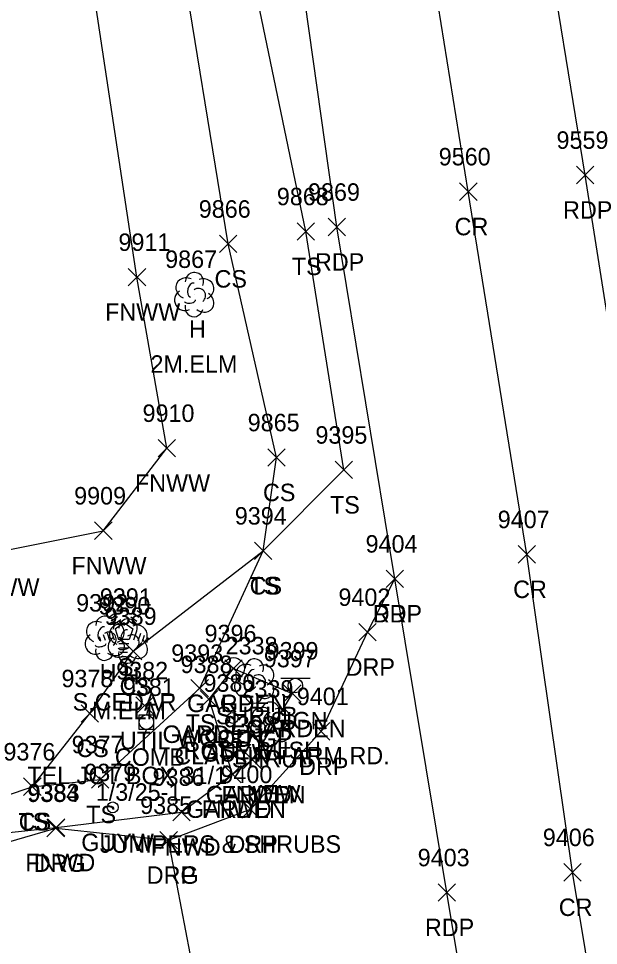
# Model space of a CAD drawing. Extents: x 1439173 to 1457902, y 641926 to 659889.
# Drawn here: x 1448183.7 to 1448250.2, y 646625.5 to 646731.6 of the extents above; entities that cross this region are included whole.
import ezdxf

# ---------------------------------------------------------------- set-up
doc = ezdxf.new("R2010")
doc.units = 0
for name, color, linetype in [('L_A', 7, 'Continuous'), ('L_C', 7, 'Continuous'), ('L_I', 7, 'Continuous'), ('L_TIC', 7, 'Continuous'), ('LAPB', 7, 'Continuous'), ('LELB', 7, 'Continuous'), ('LFNC', 7, 'Continuous'), ('LSH', 7, 'Continuous'), ('LTC', 7, 'Continuous'), ('LTD', 7, 'Continuous'), ('P_A', 7, 'Continuous'), ('P_I', 7, 'Continuous'), ('P_TIC', 7, 'Continuous'), ('PET', 7, 'Continuous'), ('PRC', 7, 'Continuous'), ('R_A', 7, 'Continuous'), ('R_I', 7, 'Continuous'), ('R_TIC', 7, 'Continuous'), ('RDG', 7, 'Continuous'), ('RDP', 7, 'Continuous'), ('RGP', 7, 'Continuous'), ('S_A', 7, 'Continuous'), ('S_C', 7, 'Continuous'), ('S_I', 7, 'Continuous'), ('SSGN', 7, 'Continuous'), ('U_A', 7, 'Continuous'), ('U_C', 7, 'Continuous'), ('U_I', 7, 'Continuous'), ('UDEFAULT', 7, 'Continuous'), ('UP', 7, 'Continuous'), ('UPGW', 7, 'Continuous')]:
    doc.layers.add(name, color=color, linetype=linetype)

msp = doc.modelspace()

# ---------------------------------------------------------------- linework, layer by layer
at = {"layer": 'L_TIC'}
for points in [[(1448215.65, 646706.27), (1448217.65, 646708.27)], [(1448217.65, 646706.27), (1448215.65, 646708.27)], [(1448206.76, 646704.84), (1448208.76, 646706.84)], [(1448208.76, 646704.84), (1448206.76, 646706.84)], [(1448196.31, 646701.04), (1448198.31, 646703.04)], [(1448198.31, 646701.04), (1448196.31, 646703.04)], [(1448199.73, 646681.46), (1448201.73, 646683.46)], [(1448201.73, 646681.46), (1448199.73, 646683.46)], [(1448212.3, 646680.39), (1448214.3, 646682.39)], [(1448214.3, 646680.39), (1448212.3, 646682.39)], [(1448220.02, 646678.97), (1448222.02, 646680.97)], [(1448222.02, 646678.97), (1448220.02, 646680.97)], [(1448220.02, 646678.97), (1448222.02, 646680.97)], [(1448222.02, 646678.97), (1448220.02, 646680.97)], [(1448192.45, 646672.01), (1448194.45, 646674.01)], [(1448194.45, 646672.01), (1448192.45, 646674.01)], [(1448210.78, 646669.71), (1448212.78, 646671.71)], [(1448212.78, 646669.71), (1448210.78, 646671.71)], [(1448210.78, 646669.71), (1448212.78, 646671.71)], [(1448212.78, 646669.71), (1448210.78, 646671.71)], [(1448195.88, 646658.22), (1448197.88, 646660.22)], [(1448197.88, 646658.22), (1448195.88, 646660.22)], [(1448207.38, 646656.24), (1448209.38, 646658.24)], [(1448209.38, 646656.24), (1448207.38, 646658.24)], [(1448203.5, 646653.99), (1448205.5, 646655.99)], [(1448205.5, 646653.99), (1448203.5, 646655.99)], [(1448214.11, 646653.37), (1448216.11, 646655.37)], [(1448216.11, 646653.37), (1448214.11, 646655.37)], [(1448204.57, 646652.71), (1448206.57, 646654.71)], [(1448206.57, 646652.71), (1448204.57, 646654.71)], [(1448190.92, 646651.09), (1448192.92, 646653.09)], [(1448192.92, 646651.09), (1448190.92, 646653.09)], [(1448209.53, 646645.79), (1448211.53, 646647.79)], [(1448211.53, 646645.79), (1448209.53, 646647.79)], [(1448209.53, 646645.79), (1448211.53, 646647.79)], [(1448211.53, 646645.79), (1448209.53, 646647.79)], [(1448192.09, 646643.53), (1448194.09, 646645.53)], [(1448194.09, 646643.53), (1448192.09, 646645.53)], [(1448207.27, 646644.13), (1448209.27, 646646.13)], [(1448209.27, 646644.13), (1448207.27, 646646.13)], [(1448207.27, 646644.13), (1448209.27, 646646.13)], [(1448209.27, 646644.13), (1448207.27, 646646.13)], [(1448184.32, 646642.7), (1448186.32, 646644.7)], [(1448186.32, 646642.7), (1448184.32, 646644.7)], [(1448184.32, 646642.7), (1448186.32, 646644.7)], [(1448186.32, 646642.7), (1448184.32, 646644.7)], [(1448201.42, 646639.8), (1448203.42, 646641.8)], [(1448203.42, 646639.8), (1448201.42, 646641.8)], [(1448187.05, 646638.02), (1448189.05, 646640.02)], [(1448189.05, 646638.02), (1448187.05, 646640.02)]]:
    msp.add_lwpolyline(points, dxfattribs=at)
at = {"layer": 'LAPB'}
msp.add_lwpolyline([(1448208.27, 646645.13), (1448205.57, 646653.71), (1448208.38, 646657.24), (1448215.11, 646654.37), (1448210.53, 646646.79)], dxfattribs=at)
at = {"layer": 'LELB'}
for points in [[(1448221.02, 646679.97), (1448216.65, 646707.27), (1448209.17, 646743.3), (1448202.24, 646783.83), (1448197.14, 646815.73), (1448192.88, 646849.23), (1448188.79, 646883.91), (1448185.57, 646916.7), (1448180.61, 646928.95), (1448176.05, 646935.8), (1448168.91, 646942.17), (1448163.03, 646939.76)], [(1448185.32, 646643.7), (1448191.92, 646652.09), (1448196.88, 646659.22), (1448211.78, 646670.71), (1448213.3, 646681.39), (1448207.76, 646705.84), (1448201.91, 646741.7), (1448196.92, 646782.31), (1448195.88, 646813.4), (1448188.29, 646849.33)], [(1448098.23, 646630.31), (1448120.23, 646632.42), (1448150.79, 646634.85), (1448163.88, 646636.49), (1448185.32, 646643.7), (1448193.09, 646644.53), (1448204.5, 646654.99), (1448211.78, 646670.71), (1448221.02, 646679.97)]]:
    msp.add_lwpolyline(points, dxfattribs=at)
at = {"layer": 'LFNC'}
for points in [[(1448099.82, 646655.95), (1448102.02, 646656.12), (1448112.07, 646658.89), (1448125.11, 646661.46), (1448146.72, 646665.17), (1448181.19, 646670.55), (1448193.45, 646673.01), (1448200.73, 646682.46), (1448197.31, 646702.04), (1448191.65, 646739.49), (1448183.01, 646786), (1448178.86, 646809.45), (1448173.13, 646841), (1448169.61, 646862.71), (1448166.95, 646881.82), (1448157.08, 646891.59), (1448153.58, 646895.82), (1448145.42, 646911.6)], [(1448163.88, 646636.49), (1448188.05, 646639.02), (1448202.42, 646640.8), (1448208.27, 646645.13), (1448210.53, 646646.79)]]:
    msp.add_lwpolyline(points, dxfattribs=at)
at = {"layer": 'LSH'}
for p, q in [((1448210.73, 646655.85), (1448210.73, 646655.85)), ((1448210.73, 646655.85), (1448210.73, 646655.85)), ((1448212.56, 646650.9), (1448212.56, 646650.9)), ((1448212.56, 646650.9), (1448212.56, 646650.9))]:
    msp.add_line(p, q, dxfattribs=at)
for centre in [(1448210.77, 646657.28), (1448212.6, 646652.34)]:
    msp.add_arc(centre, 1.05, 335.5272, 180.9563, dxfattribs=at)
for centre, major_axis, ratio, start_param, end_param in [((1448209.93, 646656.51), (1.21, -0.51), 0.895232, 1.570796, 4.712389), ((1448210.52, 646656.31), (-0.208, -0.792), 0.645439, 3.141593, 6.283185), ((1448211.77, 646656.43), (-1.14, -0.48), 0.949671, 1.570796, 4.712389), ((1448209.64, 646655.14), (0.58, -1.04), 0.959034, 3.141593, 6.283185), ((1448211.23, 646655.68), (-0.5, 0.667), 0.989748, 3.141593, 6.283185), ((1448210.27, 646655.1), (-0.625, -0.083), 0.423636, 0, 3.141593), ((1448211.73, 646655.01), (-1.09, 0.79), 0.841452, 1.570796, 4.712389), ((1448210.73, 646654.35), (0.26, 1.06), 0.942809, 1.570796, 4.712389), ((1448211.77, 646651.57), (1.21, -0.51), 0.895232, 1.570796, 4.712389), ((1448213.6, 646651.49), (-1.14, -0.48), 0.949671, 1.570796, 4.712389), ((1448212.35, 646651.36), (-0.208, -0.792), 0.645439, 3.141593, 6.283185), ((1448211.47, 646650.19), (0.58, -1.04), 0.959034, 3.141593, 6.283185), ((1448213.06, 646650.74), (-0.5, 0.667), 0.989748, 3.141593, 6.283185), ((1448213.56, 646650.07), (-1.09, 0.79), 0.841452, 1.570796, 4.712389), ((1448212.56, 646649.4), (0.26, 1.06), 0.942809, 1.570796, 4.712389), ((1448212.1, 646650.15), (-0.625, -0.083), 0.423636, 0, 3.141593)]:
    msp.add_ellipse(centre, major_axis=major_axis, ratio=ratio, start_param=start_param, end_param=end_param, dxfattribs=at)
at = {"layer": 'LTC'}
for p, q in [((1448193.95, 646663.62), (1448194.31, 646663.87)), ((1448194.16, 646663.15), (1448194.69, 646663.53)), ((1448196.98, 646663.51), (1448197.53, 646663.11)), ((1448197.35, 646663.86), (1448197.77, 646663.55)), ((1448194.37, 646662.68), (1448195.08, 646663.2)), ((1448194.58, 646662.22), (1448195.46, 646662.86)), ((1448194.81, 646661.76), (1448195.82, 646662.5)), ((1448195.82, 646662.5), (1448196.82, 646661.77)), ((1448196.24, 646662.81), (1448197.05, 646662.22)), ((1448196.61, 646663.16), (1448197.29, 646662.67)), ((1448193.9, 646661.33), (1448194.17, 646660.49)), ((1448194.35, 646661.54), (1448194.68, 646660.53)), ((1448194.81, 646661.76), (1448195.19, 646660.57)), ((1448196.82, 646661.77), (1448196.42, 646660.57)), ((1448197.25, 646661.5), (1448196.91, 646660.46)), ((1448197.7, 646661.25), (1448197.41, 646660.37)), ((1448192.99, 646660.89), (1448193.14, 646660.43)), ((1448193.44, 646661.11), (1448193.65, 646660.46)), ((1448196.42, 646660.57), (1448195.19, 646660.57)), ((1448198.14, 646661), (1448197.9, 646660.27)), ((1448198.59, 646660.75), (1448198.4, 646660.18)), ((1448196.39, 646660.07), (1448195.24, 646660.07)), ((1448196.3, 646659.57), (1448195.31, 646659.57)), ((1448196.22, 646659.07), (1448195.39, 646659.07)), ((1448196.13, 646658.57), (1448195.46, 646658.57))]:
    msp.add_line(p, q, dxfattribs=at)
at = {"layer": 'LTD'}
for p, q in [((1448203.85, 646700.09), (1448203.85, 646700.09)), ((1448203.85, 646700.09), (1448203.85, 646700.09)), ((1448193.6, 646660.75), (1448193.6, 646660.75)), ((1448193.6, 646660.75), (1448193.6, 646660.75)), ((1448196.24, 646660.42), (1448196.24, 646660.42)), ((1448196.24, 646660.42), (1448196.24, 646660.42))]:
    msp.add_line(p, q, dxfattribs=at)
for centre in [(1448203.9, 646701.52), (1448193.64, 646662.18), (1448196.29, 646661.86)]:
    msp.add_arc(centre, 1.05, 335.5272, 180.9563, dxfattribs=at)
for centre, major_axis, ratio, start_param, end_param in [((1448203.06, 646700.75), (1.21, -0.51), 0.895232, 1.570796, 4.712389), ((1448204.89, 646700.67), (-1.14, -0.48), 0.949671, 1.570796, 4.712389), ((1448203.64, 646700.55), (-0.208, -0.792), 0.645439, 3.141593, 6.283185), ((1448204.35, 646699.92), (-0.5, 0.667), 0.989748, 3.141593, 6.283185), ((1448202.77, 646699.38), (0.58, -1.04), 0.959034, 3.141593, 6.283185), ((1448204.85, 646699.25), (-1.09, 0.79), 0.841452, 1.570796, 4.712389), ((1448203.85, 646698.59), (0.26, 1.06), 0.942809, 1.570796, 4.712389), ((1448203.39, 646699.34), (-0.625, -0.083), 0.423636, 0, 3.141593), ((1448192.8, 646661.41), (1.21, -0.51), 0.895232, 1.570796, 4.712389), ((1448195.45, 646661.09), (1.21, -0.51), 0.895232, 1.570796, 4.712389), ((1448194.64, 646661.33), (-1.14, -0.48), 0.949671, 1.570796, 4.712389), ((1448197.28, 646661.01), (-1.14, -0.48), 0.949671, 1.570796, 4.712389), ((1448193.39, 646661.21), (-0.208, -0.792), 0.645439, 3.141593, 6.283185), ((1448194.1, 646660.58), (-0.5, 0.667), 0.989748, 3.141593, 6.283185), ((1448196.03, 646660.88), (-0.208, -0.792), 0.645439, 3.141593, 6.283185), ((1448192.51, 646660.04), (0.58, -1.04), 0.959034, 3.141593, 6.283185), ((1448195.16, 646659.71), (0.58, -1.04), 0.959034, 3.141593, 6.283185), ((1448194.6, 646659.91), (-1.09, 0.79), 0.841452, 1.570796, 4.712389), ((1448196.74, 646660.26), (-0.5, 0.667), 0.989748, 3.141593, 6.283185), ((1448197.24, 646659.59), (-1.09, 0.79), 0.841452, 1.570796, 4.712389), ((1448193.6, 646659.25), (0.26, 1.06), 0.942809, 1.570796, 4.712389), ((1448193.14, 646660), (-0.625, -0.083), 0.423636, 0, 3.141593), ((1448196.24, 646658.92), (0.26, 1.06), 0.942809, 1.570796, 4.712389), ((1448195.78, 646659.67), (-0.625, -0.083), 0.423636, 0, 3.141593)]:
    msp.add_ellipse(centre, major_axis=major_axis, ratio=ratio, start_param=start_param, end_param=end_param, dxfattribs=at)
at = {"layer": 'P_TIC'}
for points in [[(1448247.66, 646712.73), (1448249.66, 646714.73)], [(1448249.66, 646712.73), (1448247.66, 646714.73)], [(1448234.28, 646710.83), (1448236.28, 646712.83)], [(1448236.28, 646710.83), (1448234.28, 646712.83)], [(1448219.22, 646706.78), (1448221.22, 646708.78)], [(1448221.22, 646706.78), (1448219.22, 646708.78)], [(1448240.99, 646669.3), (1448242.99, 646671.3)], [(1448242.99, 646669.3), (1448240.99, 646671.3)], [(1448225.85, 646666.5), (1448227.85, 646668.5)], [(1448227.85, 646666.5), (1448225.85, 646668.5)], [(1448246.21, 646632.9), (1448248.21, 646634.9)], [(1448248.21, 646632.9), (1448246.21, 646634.9)], [(1448231.82, 646630.59), (1448233.82, 646632.59)], [(1448233.82, 646630.59), (1448231.82, 646632.59)]]:
    msp.add_lwpolyline(points, dxfattribs=at)
at = {"layer": 'PET'}
for points in [[(1448246.46, 646550.34), (1448240.19, 646586.21), (1448237.44, 646603.85), (1448232.82, 646631.59), (1448226.85, 646667.5), (1448220.22, 646707.78), (1448215.23, 646742.97), (1448202.82, 646783.14), (1448203.37, 646818.93), (1448198.76, 646850.24), (1448193.44, 646884.14), (1448187.94, 646917.18), (1448185.3, 646933.85), (1448181.56, 646957.89), (1448177.35, 646983.4)], [(1448276.96, 646543.22), (1448270.54, 646579.93), (1448265.59, 646610.13), (1448260.88, 646638.63), (1448255.41, 646671.17), (1448248.66, 646713.73), (1448243.76, 646743.97), (1448235.04, 646800.32), (1448226.34, 646853.04), (1448221.22, 646886.82), (1448214.61, 646928.36), (1448210.31, 646953.97), (1448206.09, 646983.02)]]:
    msp.add_lwpolyline(points, dxfattribs=at)
at = {"layer": 'PRC'}
msp.add_lwpolyline([(1448260.65, 646552.87), (1448253.95, 646593.27), (1448247.21, 646633.9), (1448241.99, 646670.3), (1448235.28, 646711.83), (1448227.36, 646761.05), (1448221.48, 646799.15), (1448208.45, 646883.94), (1448200.39, 646928.86), (1448192.53, 646980.53), (1448184.46, 647032.21), (1448180.05, 647061.28), (1448176.23, 647087.3), (1448169.96, 647123.71), (1448163.11, 647173.92), (1448157.07, 647210.64), (1448152.13, 647238.94), (1448147.96, 647264.25), (1448141.66, 647302.84), (1448134.08, 647349.96), (1448129.97, 647375), (1448122.13, 647423.97), (1448115.84, 647462.16), (1448107.04, 647514.44)], dxfattribs=at)
at = {"layer": 'R_TIC'}
for points in [[(1448225.85, 646666.5), (1448227.85, 646668.5)], [(1448227.85, 646666.5), (1448225.85, 646668.5)], [(1448222.74, 646660.4), (1448224.74, 646662.4)], [(1448224.74, 646660.4), (1448222.74, 646662.4)], [(1448217.41, 646649.04), (1448219.41, 646651.04)], [(1448219.41, 646649.04), (1448217.41, 646651.04)], [(1448209.31, 646640.11), (1448211.31, 646642.11)], [(1448211.31, 646640.11), (1448209.31, 646642.11)], [(1448187, 646637.95), (1448189, 646639.95)], [(1448189, 646637.95), (1448187, 646639.95)], [(1448199.94, 646636.58), (1448201.94, 646638.58)], [(1448201.94, 646636.58), (1448199.94, 646638.58)], [(1448199.94, 646636.58), (1448201.94, 646638.58)], [(1448201.94, 646636.58), (1448199.94, 646638.58)]]:
    msp.add_lwpolyline(points, dxfattribs=at)
at = {"layer": 'RDG'}
msp.add_lwpolyline([(1448093.77, 646626.99), (1448120.35, 646628.8), (1448151.11, 646631.73), (1448166.29, 646632.65), (1448188, 646638.95), (1448200.94, 646637.58)], dxfattribs=at)
at = {"layer": 'RDP'}
msp.add_lwpolyline([(1448237.44, 646603.85), (1448224.85, 646614.51), (1448217.13, 646619.21), (1448204.39, 646619.43), (1448200.94, 646637.58), (1448210.31, 646641.11), (1448218.41, 646650.04), (1448223.74, 646661.4), (1448226.85, 646667.5)], dxfattribs=at)
at = {"layer": 'RGP'}
msp.add_line((1448208.38, 646657.24), (1448208.38, 646657.24), dxfattribs=at)
for radius in [1.25, 0.0833]:
    msp.add_circle((1448208.38, 646657.24), radius, dxfattribs=at)
at = {"layer": 'SSGN'}
for p, q in [((1448213.81, 646656.12), (1448217.15, 646656.12)), ((1448215.46, 646655.28), (1448215.46, 646655.28))]:
    msp.add_line(p, q, dxfattribs=at)
msp.add_circle((1448215.46, 646655.28), 0.833, dxfattribs=at)
at = {"layer": 'UDEFAULT'}
for points in [[(1448197.19, 646651.99), (1448199.19, 646653.99)], [(1448199.19, 646651.99), (1448197.19, 646653.99)]]:
    msp.add_lwpolyline(points, dxfattribs=at)
at = {"layer": 'UP'}
for p, q in [((1448198.64, 646652.76), (1448198.39, 646651.93)), ((1448197.56, 646650.26), (1448197.56, 646651.93)), ((1448197.56, 646651.93), (1448199.22, 646651.93)), ((1448199.22, 646651.93), (1448199.22, 646650.26)), ((1448198.39, 646651.09), (1448198.39, 646651.09)), ((1448199.22, 646650.26), (1448197.56, 646650.26)), ((1448198.14, 646649.43), (1448198.39, 646650.26))]:
    msp.add_line(p, q, dxfattribs=at)
msp.add_circle((1448198.39, 646651.09), 0.833, dxfattribs=at)
at = {"layer": 'UPGW'}
for centre, radius in [((1448208.27, 646651.57), 0.625), ((1448208.27, 646651.57), 0.0833), ((1448194.54, 646641.33), 0.625), ((1448194.54, 646641.33), 0.0833)]:
    msp.add_circle(centre, radius, dxfattribs=at)

# ---------------------------------------------------------------- texts
at = {"layer": 'L_A'}
for s, p in [('TS', (1448215.06, 646702.27)), ('CS', (1448206.2, 646700.84)), ('FNWW', (1448193.66, 646697.04)), ('H', (1448203.28, 646695.09)), ('FNWW', (1448197.08, 646677.46)), ('CS', (1448211.75, 646676.39)), ('TS', (1448219.43, 646674.97)), ('TS', (1448219.43, 646674.97)), ('FNWW', (1448189.8, 646668.01)), ('TS', (1448210.19, 646665.71)), ('CS', (1448210.22, 646665.71)), ('FNWW', (1448177.53, 646665.55)), ('S', (1448195.14, 646656.41)), ('H', (1448193.03, 646655.75)), ('H', (1448195.67, 646655.42)), ('CS', (1448195.32, 646654.22)), ('GARDEN', (1448203.05, 646652.24)), ('SHRUB', (1448206.36, 646650.85)), ('TS', (1448202.9, 646649.99)), ('GARDEN', (1448200.24, 646648.71)), ('GARDEN', (1448209.78, 646649.37)), ('CS', (1448190.36, 646647.09)), ('SHRUB', (1448208.19, 646645.9)), ('GARDEN', (1448205.2, 646641.79)), ('FNWD', (1448207, 646641.79)), ('GARDEN', (1448202.94, 646640.13)), ('TS', (1448191.5, 646639.53)), ('FNWD', (1448204.73, 646640.13)), ('TS', (1448183.73, 646638.7)), ('CS', (1448183.76, 646638.7)), ('FNWD', (1448198.88, 646635.8)), ('FNWD', (1448184.51, 646634.02))]:
    msp.add_text(s, height=2, dxfattribs=at).set_placement(p)
at = {"layer": 'L_C'}
for s, p in [('2M.ELM', (1448198.86, 646691.09)), ('S.CEDAR', (1448189.94, 646652.41)), ('M.ELM', (1448192.15, 646651.42)), ('WOOD GP', (1448201.9, 646648.24)), ('ROSE BUSH', (1448202.65, 646646.85)), ('YEW', (1448209.96, 646641.9)), ('JUNIPERS & SHRUBS', (1448193.06, 646636.13))]:
    msp.add_text(s, height=2, dxfattribs=at).set_placement(p)
at = {"layer": 'L_I'}
for s, p in [('9868', (1448213.34, 646710.27)), ('9866', (1448204.39, 646708.84)), ('9911', (1448195.19, 646705.04)), ('9867', (1448200.54, 646703.09)), ('9910', (1448197.95, 646685.46)), ('9865', (1448210, 646684.39)), ('9395', (1448217.76, 646682.97)), ('9395', (1448217.76, 646682.97)), ('9909', (1448190.11, 646676.01)), ('9394', (1448208.52, 646673.71)), ('9394', (1448208.52, 646673.71)), ('9392', (1448190.34, 646663.75)), ('9391', (1448193.06, 646664.41)), ('9390', (1448192.9, 646663.42)), ('9389', (1448193.61, 646662.22)), ('9396', (1448205.06, 646660.24)), ('2338', (1448207.47, 646658.85)), ('9393', (1448201.24, 646657.99)), ('9397', (1448211.85, 646657.37)), ('9388', (1448202.31, 646656.71)), ('9378', (1448188.66, 646655.09)), ('2339', (1448209.29, 646653.9)), ('9398', (1448207.27, 646649.79)), ('9398', (1448207.27, 646649.79)), ('9387', (1448205.01, 646648.13)), ('9387', (1448205.01, 646648.13)), ('9376', (1448182.01, 646646.7)), ('9376', (1448182.01, 646646.7)), ('9377', (1448189.83, 646647.53)), ('9386', (1448199.1, 646643.8)), ('9383', (1448184.79, 646642.02))]:
    msp.add_text(s, height=2, dxfattribs=at).set_placement(p)
at = {"layer": 'LTC'}
msp.add_text('.', height=1.04, rotation=270, dxfattribs=at).set_placement((1448195.7, 646661.51))
at = {"layer": 'P_A'}
for s, p in [('RDP', (1448246.14, 646708.73)), ('CR', (1448233.71, 646706.83)), ('RDP', (1448217.71, 646702.78)), ('CR', (1448240.42, 646665.3)), ('RDP', (1448224.33, 646662.5)), ('CR', (1448245.65, 646628.9)), ('RDP', (1448230.31, 646626.59))]:
    msp.add_text(s, height=2, dxfattribs=at).set_placement(p)
at = {"layer": 'P_I'}
for s, p in [('9559', (1448245.39, 646716.73)), ('9560', (1448231.89, 646714.83)), ('9869', (1448216.91, 646710.78)), ('9407', (1448238.65, 646673.3)), ('9404', (1448223.51, 646670.5)), ('9406', (1448243.82, 646636.9)), ('9403', (1448229.48, 646634.59))]:
    msp.add_text(s, height=2, dxfattribs=at).set_placement(p)
at = {"layer": 'R_A'}
for s, p in [('DRP', (1448224.33, 646662.5)), ('DRP', (1448221.23, 646656.4)), ('GP', (1448206.81, 646652.24)), ('DRP', (1448215.89, 646645.04)), ('DRP', (1448207.8, 646636.11)), ('DRG', (1448185.49, 646633.95)), ('DRG', (1448198.43, 646632.58)), ('DRP', (1448198.43, 646632.58))]:
    msp.add_text(s, height=2, dxfattribs=at).set_placement(p)
at = {"layer": 'R_I'}
for s, p in [('9404', (1448223.51, 646670.5)), ('9402', (1448220.4, 646664.4)), ('9396', (1448205.06, 646660.24)), ('9401', (1448215.63, 646653.04)), ('9400', (1448206.88, 646644.11)), ('9384', (1448184.74, 646641.95)), ('9385', (1448197.68, 646640.58)), ('9385', (1448197.68, 646640.58))]:
    msp.add_text(s, height=2, dxfattribs=at).set_placement(p)
at = {"layer": 'S_A'}
msp.add_text('SIGN', height=2, dxfattribs=at).set_placement((1448212.6, 646650.26))
at = {"layer": 'S_C'}
msp.add_text('CLAFLIN FARM RD.', height=2, dxfattribs=at).set_placement((1448201.6, 646646.26))
at = {"layer": 'S_I'}
msp.add_text('9399', height=2, dxfattribs=at).set_placement((1448212.17, 646658.26))
at = {"layer": 'U_A'}
for s, p in [('UTIL', (1448195.35, 646647.99)), ('GUYW', (1448204.67, 646646.57)), ('COMB', (1448194.78, 646646.09)), ('GUYW', (1448190.93, 646636.33))]:
    msp.add_text(s, height=2, dxfattribs=at).set_placement(p)
at = {"layer": 'U_C'}
for s, p in [('TEL JCT BOX 31/1', (1448184.75, 646643.99)), ('1/3/25-1', (1448192.59, 646642.09))]:
    msp.add_text(s, height=2, dxfattribs=at).set_placement(p)
at = {"layer": 'U_I'}
for s, p in [('9382', (1448194.93, 646655.99)), ('9381', (1448195.7, 646654.09)), ('9380', (1448204.93, 646654.57)), ('9379', (1448191.27, 646644.33))]:
    msp.add_text(s, height=2, dxfattribs=at).set_placement(p)

doc.saveas('drawing.dxf')
